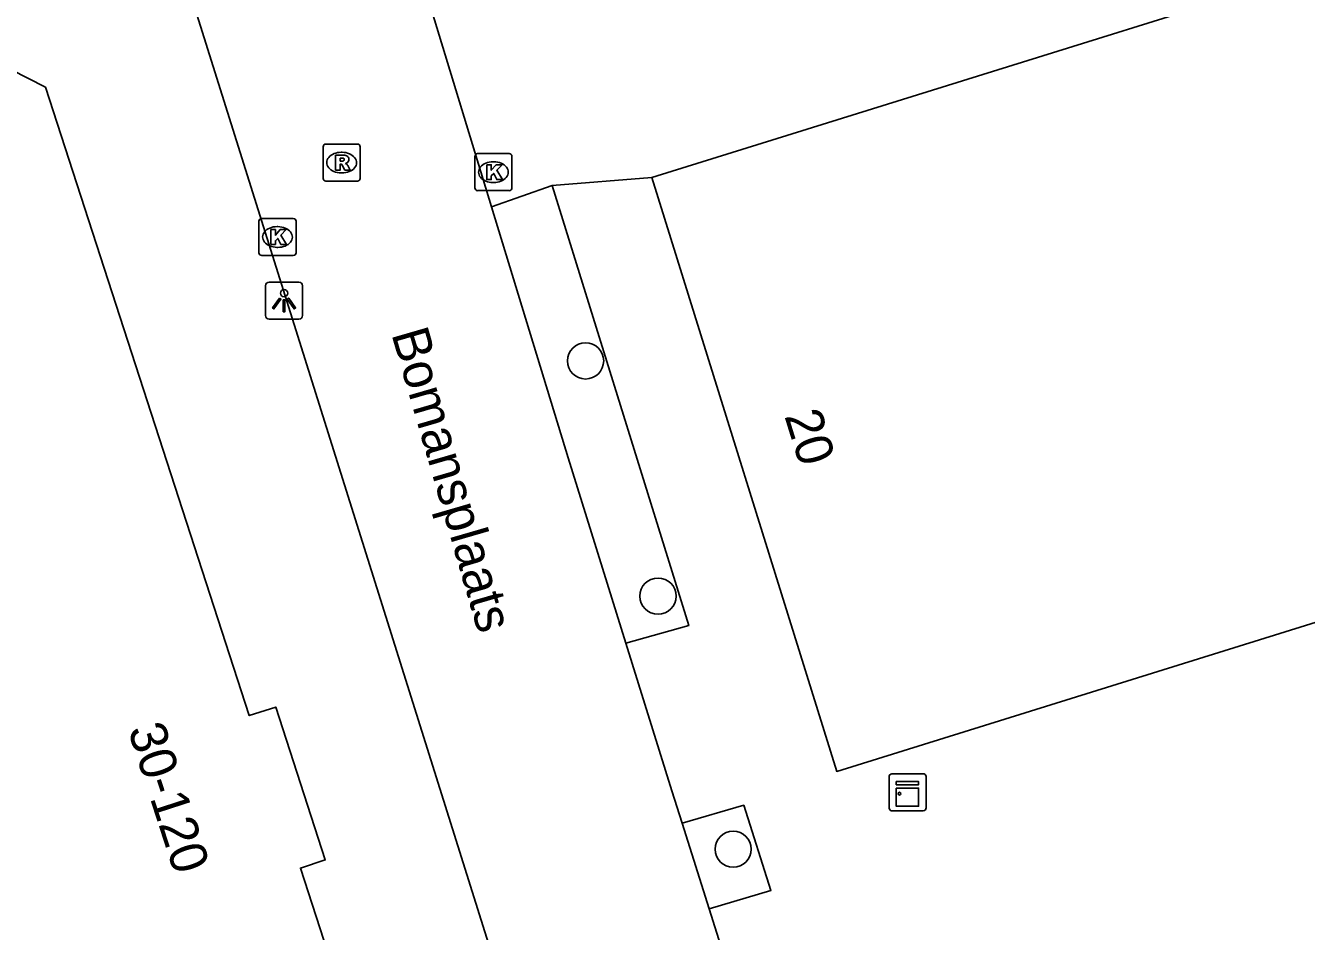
# Model space of a CAD drawing. Extents: x 161354 to 161876, y 382161 to 382804.
# Drawn here: x 161724.32 to 161758.92, y 382447.49 to 382471.95 of the extents above; entities that cross this region are included whole.
import ezdxf

# ---------------------------------------------------------------- set-up
doc = ezdxf.new("R2010")
doc.units = 0
for name, color, linetype in [('IMGEO_Boom', 7, 'Continuous'), ('IMGEO_Kast', 7, 'Continuous'), ('IMGEO_Kolk', 7, 'Continuous'), ('IMGEO_Lichtpunt', 7, 'Continuous'), ('IMGEO_Openbare_ruimte_label', 7, 'Continuous'), ('IMGEO_Pand', 7, 'Continuous'), ('IMGEO_Pand_nummerreeks', 7, 'Continuous'), ('IMGEO_Rijbaan_lokaal_open', 7, 'Continuous'), ('IMGEO_Rioolput', 7, 'Continuous'), ('IMGEO_Voetpad_open', 7, 'Continuous')]:
    doc.layers.add(name, color=color, linetype=linetype)

msp = doc.modelspace()

# ---------------------------------------------------------------- linework, layer by layer
at = {"layer": 'IMGEO_Boom'}
for centre in [(161739.449, 382462.895), (161741.405, 382456.543), (161743.435, 382449.708)]:
    msp.add_circle(centre, 0.489, dxfattribs=at)
at = {"layer": 'IMGEO_Kast'}
for p, q in [((161747.647, 382450.819), (161747.647, 382451.66)), ((161747.647, 382451.66), (161747.647, 382450.819)), ((161747.722, 382451.744), (161748.563, 382451.744)), ((161748.563, 382451.744), (161747.722, 382451.744)), ((161748.647, 382451.669), (161748.647, 382450.828)), ((161748.647, 382450.828), (161748.647, 382451.669)), ((161748.572, 382450.744), (161747.731, 382450.744)), ((161747.731, 382450.744), (161748.572, 382450.744))]:
    msp.add_line(p, q, dxfattribs=at)
for points in [[(161747.842, 382451.534), (161748.442, 382451.534), (161748.442, 382451.449), (161747.842, 382451.449), (161747.842, 382451.534)], [(161747.842, 382451.359), (161748.442, 382451.359), (161748.442, 382450.87), (161747.842, 382450.87), (161747.842, 382451.359)]]:
    msp.add_lwpolyline(points, dxfattribs=at)
msp.add_circle((161747.926, 382451.208), 0.0377, dxfattribs=at)
for centre, start, end in [((161747.725, 382451.666), 92.4484, 184.2845), ((161747.725, 382451.666), 92.4484, 184.2845), ((161748.569, 382451.666), 2.4484, 94.2845), ((161748.569, 382451.666), 2.4484, 94.2845), ((161747.725, 382450.822), 182.4484, 274.2845), ((161747.725, 382450.822), 182.4484, 274.2845), ((161748.569, 382450.822), 272.4484, 4.2845), ((161748.569, 382450.822), 272.4484, 4.2845)]:
    msp.add_arc(centre, 0.0779, start, end, dxfattribs=at)
at = {"layer": 'IMGEO_Kolk'}
for p, q in [((161736.458, 382467.567), (161736.458, 382468.419)), ((161736.533, 382468.493), (161737.385, 382468.493)), ((161736.946, 382468.273), (161736.971, 382468.273)), ((161737.459, 382468.419), (161737.459, 382467.567)), ((161737.385, 382467.493), (161736.533, 382467.493)), ((161736.969, 382467.713), (161736.944, 382467.713)), ((161730.626, 382465.815), (161730.626, 382466.667)), ((161730.701, 382466.741), (161731.553, 382466.741)), ((161731.114, 382466.521), (161731.139, 382466.521)), ((161731.627, 382466.667), (161731.627, 382465.815)), ((161731.137, 382465.961), (161731.112, 382465.961)), ((161731.553, 382465.741), (161730.701, 382465.741))]:
    msp.add_line(p, q, dxfattribs=at)
for points in [[(161736.458, 382467.567), (161736.458, 382468.419)], [(161736.533, 382468.493), (161737.385, 382468.493)], [(161736.779, 382468.193), (161736.902, 382468.193), (161736.902, 382468.042), (161737.032, 382468.193), (161737.196, 382468.193), (161737.05, 382468.042), (161737.203, 382467.793), (161737.051, 382467.793), (161736.966, 382467.957), (161736.902, 382467.89), (161736.902, 382467.793), (161736.779, 382467.793), (161736.779, 382468.193)], [(161737.459, 382468.419), (161737.459, 382467.567)], [(161737.385, 382467.493), (161736.533, 382467.493)], [(161730.626, 382465.815), (161730.626, 382466.667)], [(161730.701, 382466.741), (161731.553, 382466.741)], [(161731.627, 382466.667), (161731.627, 382465.815)], [(161730.947, 382466.441), (161731.07, 382466.441), (161731.07, 382466.29), (161731.2, 382466.441), (161731.364, 382466.441), (161731.218, 382466.29), (161731.371, 382466.041), (161731.219, 382466.041), (161731.134, 382466.205), (161731.07, 382466.138), (161731.07, 382466.041), (161730.947, 382466.041), (161730.947, 382466.441)], [(161731.553, 382465.741), (161730.701, 382465.741)]]:
    msp.add_lwpolyline(points, dxfattribs=at)
for centre, start, end in [((161736.535, 382468.417), 91.552, 178.448), ((161736.535, 382468.417), 91.552, 178.448), ((161737.383, 382468.417), 1.552, 88.448), ((161737.383, 382468.417), 1.552, 88.448), ((161736.535, 382467.569), 181.552, 268.448), ((161736.535, 382467.569), 181.552, 268.448), ((161737.383, 382467.569), 271.552, 358.448), ((161737.383, 382467.569), 271.552, 358.448), ((161730.703, 382466.665), 91.552, 178.448), ((161730.703, 382466.665), 91.552, 178.448), ((161731.551, 382466.665), 1.552, 88.448), ((161731.551, 382466.665), 1.552, 88.448), ((161730.703, 382465.817), 181.552, 268.448), ((161730.703, 382465.817), 181.552, 268.448), ((161731.551, 382465.817), 271.552, 358.448), ((161731.551, 382465.817), 271.552, 358.448)]:
    msp.add_arc(centre, 0.0765, start, end, dxfattribs=at)
for centre, major_axis, ratio, start_param, end_param in [((161736.945, 382467.993), (-0.387, 0.002), 0.722429, 4.712389, 7.853982), ((161736.97, 382467.993), (-0.39, 0.002), 0.717154, 1.570796, 4.712389), ((161731.113, 382466.241), (-0.387, 0.002), 0.722429, 4.712389, 7.853982), ((161731.138, 382466.241), (-0.39, 0.002), 0.717154, 1.570796, 4.712389)]:
    msp.add_ellipse(centre, major_axis=major_axis, ratio=ratio, start_param=start_param, end_param=end_param, dxfattribs=at)
at = {"layer": 'IMGEO_Lichtpunt'}
for p, q in [((161730.805, 382464.927), (161730.805, 382464.12)), ((161730.805, 382464.927), (161730.805, 382464.12)), ((161731.707, 382465.022), (161730.899, 382465.022)), ((161731.707, 382465.022), (161730.899, 382465.022)), ((161731.801, 382464.12), (161731.801, 382464.927)), ((161731.801, 382464.12), (161731.801, 382464.927)), ((161730.899, 382464.026), (161731.707, 382464.026)), ((161730.899, 382464.026), (161731.707, 382464.026))]:
    msp.add_line(p, q, dxfattribs=at)
for points in [[(161731.179, 382464.591), (161731.218, 382464.563), (161731.03, 382464.301), (161730.992, 382464.328), (161731.179, 382464.591)], [(161731.281, 382464.543), (161731.328, 382464.543), (161731.328, 382464.221), (161731.281, 382464.221), (161731.281, 382464.543)], [(161731.391, 382464.563), (161731.429, 382464.59), (161731.616, 382464.328), (161731.577, 382464.3), (161731.391, 382464.563)]]:
    msp.add_lwpolyline(points, dxfattribs=at)
msp.add_circle((161731.304, 382464.725), 0.0994, dxfattribs=at)
for centre, start, end in [((161730.899, 382464.927), 90, 180), ((161730.899, 382464.927), 90, 180), ((161731.707, 382464.927), 0, 90), ((161731.707, 382464.927), 0, 90), ((161730.899, 382464.12), 180, 270), ((161730.899, 382464.12), 180, 270), ((161731.707, 382464.12), 270, 0), ((161731.707, 382464.12), 270, 360)]:
    msp.add_arc(centre, 0.0946, start, end, dxfattribs=at)
at = {"layer": 'IMGEO_Pand'}
for points in [[(161741.239, 382467.848), (161766.816, 382475.812), (161767.193, 382474.599), (161779.657, 382478.48), (161779.28, 382479.692)], [(161710.691, 382461.109), (161709.35, 382465.246), (161709.907, 382466.336), (161715.568, 382468.172), (161715.427, 382468.608), (161718.182, 382469.502), (161718.358, 382468.959), (161723.923, 382470.764), (161724.862, 382470.285), (161730.364, 382453.315), (161731.079, 382453.547), (161732.418, 382449.418), (161731.746, 382449.2), (161737.439, 382431.641), (161730.745, 382429.471), (161730.895, 382429.009)], [(161781.784, 382462.878), (161780.635, 382462.52), (161746.233, 382451.809), (161741.239, 382467.848)]]:
    msp.add_lwpolyline(points, dxfattribs=at)
at = {"layer": 'IMGEO_Rijbaan_lokaal_open'}
for points in [[(161727.934, 382475.503), (161740.031, 382436.95)], [(161734.468, 382475.066), (161736.911, 382467.053)], [(161736.911, 382467.053), (161738.977, 382460.274), (161740.535, 382455.275)], [(161740.535, 382455.275), (161741.778, 382451.285), (161742.055, 382450.408)], [(161742.055, 382450.408), (161742.785, 382448.094)], [(161742.785, 382448.094), (161745.334, 382440.013)]]:
    msp.add_lwpolyline(points, dxfattribs=at)
at = {"layer": 'IMGEO_Rioolput'}
for p, q in [((161732.359, 382467.824), (161732.359, 382468.676)), ((161732.434, 382468.75), (161733.286, 382468.75)), ((161732.847, 382468.53), (161732.872, 382468.53)), ((161733.36, 382468.676), (161733.36, 382467.824)), ((161732.87, 382467.97), (161732.845, 382467.97)), ((161733.286, 382467.75), (161732.434, 382467.75))]:
    msp.add_line(p, q, dxfattribs=at)
for points in [[(161732.359, 382467.824), (161732.359, 382468.676)], [(161732.434, 382468.75), (161733.286, 382468.75)], [(161733.36, 382468.676), (161733.36, 382467.824)], [(161732.948, 382468.448), (161732.696, 382468.45), (161732.696, 382468.05)], [(161732.696, 382468.05), (161732.82, 382468.05), (161732.82, 382468.212), (161732.831, 382468.212)], [(161732.874, 382468.369), (161732.82, 382468.369), (161732.82, 382468.288)], [(161732.82, 382468.288), (161732.872, 382468.288)], [(161732.878, 382468.183), (161732.949, 382468.05), (161733.089, 382468.05), (161733.024, 382468.176)], [(161733.286, 382467.75), (161732.434, 382467.75)]]:
    msp.add_lwpolyline(points, dxfattribs=at)
for centre, radius, start, end in [((161732.436, 382468.674), 0.0765, 91.552, 178.448), ((161732.436, 382468.674), 0.0765, 91.552, 178.448), ((161733.284, 382468.674), 0.0765, 1.552, 88.448), ((161733.284, 382468.674), 0.0765, 1.552, 88.448), ((161732.83, 382468.159), 0.0533, 26.0293, 88.6989), ((161732.856, 382468.477), 0.19, 274.7715, 282.9687), ((161732.88, 382468.273), 0.0964, 77.0061, 93.1865), ((161732.894, 382468.33), 0.0378, 276.6634, 79.6772), ((161732.947, 382468.338), 0.109, 350.3612, 89.416), ((161732.945, 382468.338), 0.112, 277.5842, 350.9817), ((161732.929, 382468.123), 0.108, 29.5134, 73.7905), ((161732.436, 382467.826), 0.0765, 181.552, 268.448), ((161732.436, 382467.826), 0.0765, 181.552, 268.448), ((161733.284, 382467.826), 0.0765, 271.552, 358.448), ((161733.284, 382467.826), 0.0765, 271.552, 358.448)]:
    msp.add_arc(centre, radius, start, end, dxfattribs=at)
for centre, major_axis, ratio, start_param, end_param in [((161732.846, 382468.25), (-0.387, 0.002), 0.722429, 4.712389, 7.853982), ((161732.871, 382468.25), (-0.39, 0.002), 0.717154, 1.570796, 4.712389)]:
    msp.add_ellipse(centre, major_axis=major_axis, ratio=ratio, start_param=start_param, end_param=end_param, dxfattribs=at)
at = {"layer": 'IMGEO_Voetpad_open'}
for points in [[(161741.239, 382467.848), (161738.546, 382467.628)], [(161738.546, 382467.628), (161736.911, 382467.053)], [(161738.546, 382467.628), (161742.236, 382455.745), (161740.535, 382455.275)], [(161742.055, 382450.408), (161743.72, 382450.897), (161744.454, 382448.592), (161742.785, 382448.094)]]:
    msp.add_lwpolyline(points, dxfattribs=at)

# ---------------------------------------------------------------- texts
at = {"layer": 'IMGEO_Openbare_ruimte_label'}
msp.add_text('Bomansplaats', height=1, rotation=286.2052, dxfattribs=at).set_placement((161734.198, 382463.628))
at = {"layer": 'IMGEO_Pand_nummerreeks'}
for s, rotation, p in [('20', 287.2948, (161744.814, 382461.413)), ('30-120', 287.95, (161727.079, 382452.937))]:
    msp.add_text(s, height=1, rotation=rotation, dxfattribs=at).set_placement(p)

doc.saveas('drawing.dxf')
